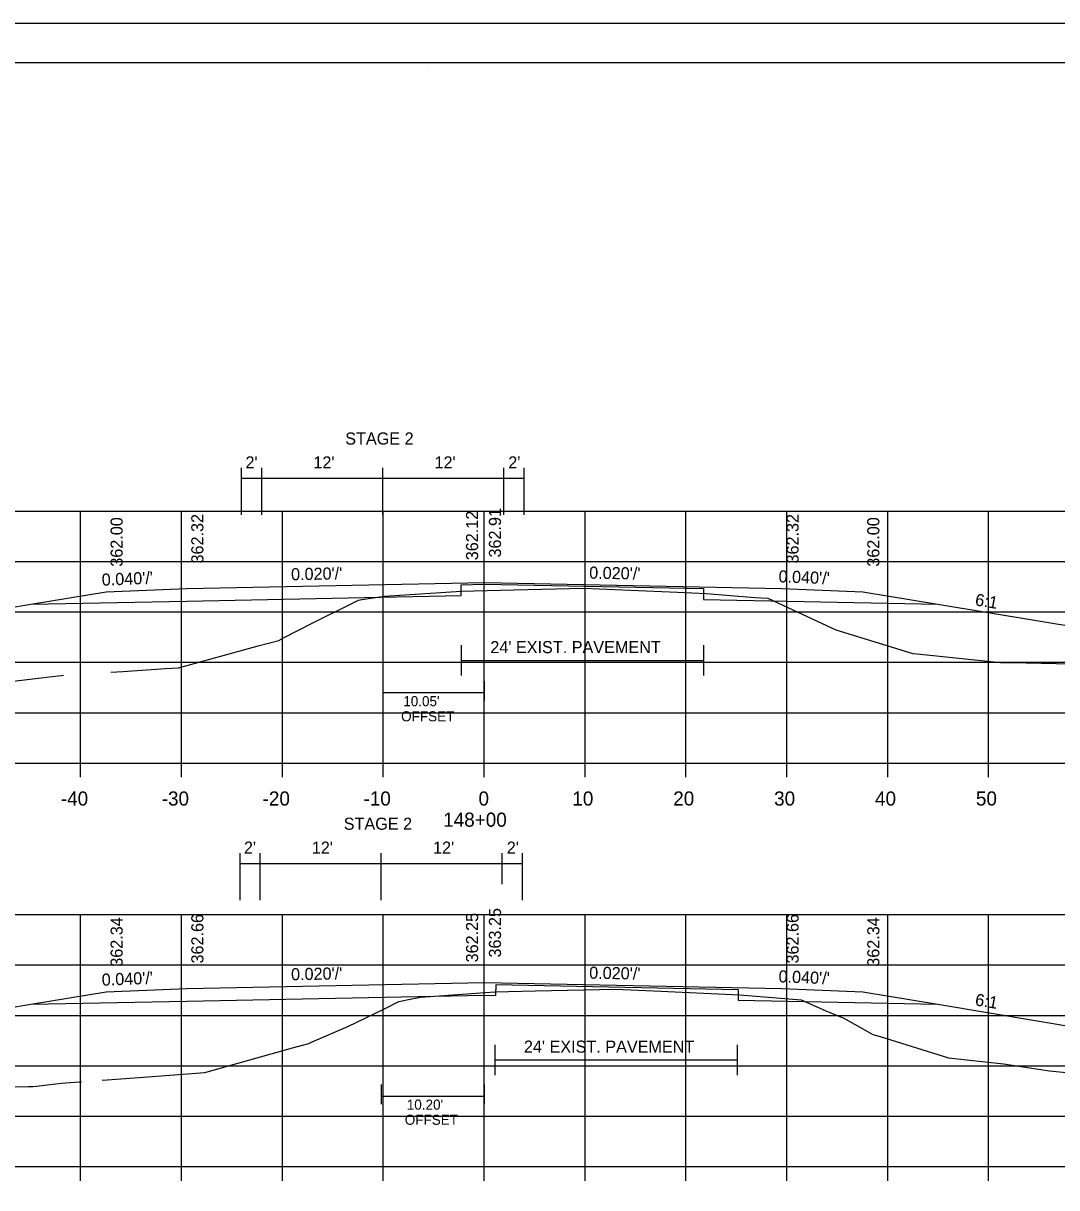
# Model space of a CAD drawing. Extents: x 1374859 to 1376773, y 382242 to 389804.
# Drawn here: x 1376088.9 to 1376191.3, y 386393.1 to 386508.5 of the extents above; entities that cross this region are included whole.
import ezdxf

# ---------------------------------------------------------------- set-up
doc = ezdxf.new("R2010")
doc.units = 0
for name, color, linetype in [('R_Axis', 7, 'Continuous'), ('R_Axis Annot', 7, 'Continuous'), ('R_Border', 7, 'Continuous'), ('R_Border Notes', 7, 'Continuous'), ('R_Draft', 7, 'Continuous'), ('R_Exist Surface', 7, 'Continuous'), ('R_Fin Surface', 7, 'Continuous'), ('R_Grid', 7, 'Continuous'), ('R_MOT', 7, 'Continuous'), ('R_No Plot', 7, 'Continuous'), ('R_Xsect Elev', 7, 'Continuous'), ('R_Xsect Slope', 7, 'Continuous')]:
    doc.layers.add(name, color=color, linetype=linetype)

msp = doc.modelspace()

# ---------------------------------------------------------------- linework, layer by layer
at = {"layer": 'R_Axis'}
for p, q in [((1375994.57, 386435.14), (1376274.57, 386435.14)), ((1376094.57, 386433.74), (1376094.57, 386435.14)), ((1376104.57, 386433.74), (1376104.57, 386435.14)), ((1376114.57, 386433.74), (1376114.57, 386435.14)), ((1376124.57, 386433.74), (1376124.57, 386435.14)), ((1376134.57, 386433.74), (1376134.57, 386435.14)), ((1376144.57, 386433.74), (1376144.57, 386435.14)), ((1376154.57, 386433.74), (1376154.57, 386435.14)), ((1376164.57, 386433.74), (1376164.57, 386435.14)), ((1376174.57, 386433.74), (1376174.57, 386435.14)), ((1376184.57, 386433.74), (1376184.57, 386435.14)), ((1375994.57, 386395.14), (1376274.57, 386395.14)), ((1376094.57, 386393.74), (1376094.57, 386395.14)), ((1376104.57, 386393.74), (1376104.57, 386395.14)), ((1376114.57, 386393.74), (1376114.57, 386395.14)), ((1376124.57, 386393.74), (1376124.57, 386395.14)), ((1376134.57, 386393.74), (1376134.57, 386395.14)), ((1376144.57, 386393.74), (1376144.57, 386395.14)), ((1376154.57, 386393.74), (1376154.57, 386395.14)), ((1376164.57, 386393.74), (1376164.57, 386395.14)), ((1376174.57, 386393.74), (1376174.57, 386395.14)), ((1376184.57, 386393.74), (1376184.57, 386395.14))]:
    msp.add_line(p, q, dxfattribs=at)
at = {"layer": 'R_Border'}
for p, q in [((1375976.57, 386504.6), (1376292.75, 386504.6)), ((1376129.09, 386504.34), (1376129.09, 386504.34)), ((1376129.09, 386504.34), (1376129.09, 386504.34))]:
    msp.add_line(p, q, dxfattribs=at)
at = {"layer": 'R_Border Notes'}
for points in [[(1376132.3, 386446.83), (1376132.3, 386443.83)], [(1376156.31, 386446.83), (1376156.31, 386443.83)], [(1376132.3, 386445.33), (1376156.31, 386445.33)], [(1376135.64, 386407.22), (1376135.64, 386404.22)], [(1376159.64, 386407.22), (1376159.64, 386404.22)], [(1376135.64, 386405.72), (1376159.64, 386405.72)]]:
    msp.add_lwpolyline(points, dxfattribs=at)
at = {"layer": 'R_Exist Surface'}
for points in [[(1376097.56, 386444.18), (1376098.76, 386444.22), (1376103, 386444.52), (1376104.27, 386444.6), (1376112.17, 386446.77), (1376114.22, 386447.3), (1376114.69, 386447.56), (1376117.58, 386449.05), (1376121.58, 386451.04), (1376122.11, 386451.3), (1376122.45, 386451.36), (1376124.68, 386451.7), (1376127.22, 386451.87), (1376132.3, 386452.21), (1376136.17, 386452.3), (1376144.4, 386452.49), (1376153.73, 386452.1), (1376156.59, 386451.98), (1376161.41, 386451.58), (1376162.68, 386451.49), (1376167.09, 386449.45), (1376169.44, 386448.35), (1376177.06, 386446.03), (1376177.1, 386446.02), (1376177.48, 386445.98), (1376185.75, 386445.11), (1376188.3, 386445.09), (1376192.83, 386444.99)], [(1375994.57, 386442.8), (1376007.7, 386442.84), (1376008.26, 386442.83), (1376009.05, 386442.83), (1376029.01, 386443.01), (1376032.33, 386442.98), (1376047.5, 386442.94), (1376059.44, 386442.96), (1376065.56, 386443.09), (1376078.87, 386443.14), (1376082.7, 386443.16), (1376085.49, 386443.17), (1376086.97, 386443.17), (1376087.2, 386443.17), (1376087.37, 386443.2), (1376090.65, 386443.6), (1376091.79, 386443.74), (1376092.36, 386443.81), (1376092.66, 386443.84), (1376092.86, 386443.86)], [(1376096.7, 386403.71), (1376097.19, 386403.75), (1376098.1, 386403.82), (1376100.37, 386403.98), (1376106.87, 386404.47), (1376115.58, 386406.91), (1376117.19, 386407.36), (1376117.52, 386407.5), (1376121.05, 386409.03), (1376124.68, 386410.8), (1376126.1, 386411.51), (1376127.39, 386411.78), (1376128.26, 386411.96), (1376133.33, 386412.31), (1376135.64, 386412.46), (1376139.67, 386412.56), (1376147.58, 386412.73), (1376151.37, 386412.57), (1376159.9, 386412.19), (1376163.54, 386411.89), (1376166, 386411.69), (1376168.45, 386410.59), (1376170.23, 386409.87), (1376172.87, 386408.39), (1376173.1, 386408.25), (1376173.81, 386408.03), (1376180.6, 386405.94), (1376186.03, 386405.33), (1376190.62, 386404.64), (1376193.61, 386404.34)], [(1375994.57, 386402.62), (1376001.33, 386402.64), (1376009.06, 386402.67), (1376011.46, 386402.68), (1376019.91, 386402.72), (1376032.69, 386402.78), (1376039.85, 386402.82), (1376050.5, 386402.85), (1376063.28, 386402.91), (1376068.8, 386402.93), (1376073.68, 386402.96), (1376085.94, 386403.06), (1376089.36, 386403.09), (1376089.82, 386403.08), (1376090.21, 386403.12), (1376092.67, 386403.41), (1376093.97, 386403.51), (1376094.47, 386403.55), (1376094.67, 386403.56)]]:
    msp.add_lwpolyline(points, dxfattribs=at)
at = {"layer": 'R_Fin Surface'}
for points in [[(1376048.6, 386442.95), (1376053.55, 386441.3), (1376075.09, 386448.48), (1376089.65, 386450.9), (1376097.09, 386452.14), (1376105.09, 386452.46), (1376134.59, 386453.05), (1376164.09, 386452.46), (1376172.09, 386452.14), (1376179.52, 386450.9), (1376194.09, 386448.48), (1376212.49, 386442.34), (1376218.21, 386444.25)], [(1376089.65, 386450.9), (1376105.1, 386451.21), (1376132.3, 386451.76), (1376132.3, 386452.84), (1376134.58, 386452.88), (1376156.31, 386452.45), (1376156.31, 386451.37), (1376179.52, 386450.9)], [(1376046.76, 386402.84), (1376051.96, 386401.1), (1376075.09, 386408.81), (1376089.65, 386411.24), (1376097.09, 386412.48), (1376105.09, 386412.8), (1376134.59, 386413.39), (1376164.09, 386412.8), (1376172.09, 386412.48), (1376179.52, 386411.24), (1376194.09, 386408.81), (1376214.1, 386402.14), (1376220.65, 386404.32)], [(1376134.58, 386412.14), (1376135.74, 386412.12), (1376135.75, 386413.2), (1376159.75, 386412.72), (1376159.76, 386411.64), (1376179.51, 386411.24)], [(1376089.65, 386411.24), (1376105.1, 386411.55), (1376134.58, 386412.14)]]:
    msp.add_lwpolyline(points, dxfattribs=at)
at = {"layer": 'R_Grid'}
for p, q in [((1375994.57, 386460.14), (1376274.57, 386460.14)), ((1376094.57, 386435.14), (1376094.57, 386460.14)), ((1376104.57, 386435.14), (1376104.57, 386460.14)), ((1376114.57, 386435.14), (1376114.57, 386460.14)), ((1376124.57, 386435.14), (1376124.57, 386460.14)), ((1376134.57, 386435.14), (1376134.57, 386460.14)), ((1376144.57, 386435.14), (1376144.57, 386460.14)), ((1376154.57, 386435.14), (1376154.57, 386460.14)), ((1376164.57, 386435.14), (1376164.57, 386460.14)), ((1376174.57, 386435.14), (1376174.57, 386460.14)), ((1376184.57, 386435.14), (1376184.57, 386460.14)), ((1375994.57, 386455.14), (1376274.57, 386455.14)), ((1375994.57, 386450.14), (1376274.57, 386450.14)), ((1375994.57, 386445.14), (1376274.57, 386445.14)), ((1375994.57, 386440.14), (1376274.57, 386440.14)), ((1375994.57, 386435.14), (1376274.57, 386435.14)), ((1375994.57, 386420.14), (1376274.57, 386420.14)), ((1376094.57, 386395.14), (1376094.57, 386420.14)), ((1376104.57, 386395.14), (1376104.57, 386420.14)), ((1376114.57, 386395.14), (1376114.57, 386420.14)), ((1376124.57, 386395.14), (1376124.57, 386420.14)), ((1376134.57, 386395.14), (1376134.57, 386420.14)), ((1376144.57, 386395.14), (1376144.57, 386420.14)), ((1376154.57, 386395.14), (1376154.57, 386420.14)), ((1376164.57, 386395.14), (1376164.57, 386420.14)), ((1376174.57, 386395.14), (1376174.57, 386420.14)), ((1376184.57, 386395.14), (1376184.57, 386420.14)), ((1375994.57, 386415.14), (1376274.57, 386415.14)), ((1375994.57, 386410.14), (1376274.57, 386410.14)), ((1375994.57, 386405.14), (1376274.57, 386405.14)), ((1375994.57, 386400.14), (1376274.57, 386400.14)), ((1375994.57, 386395.14), (1376274.57, 386395.14))]:
    msp.add_line(p, q, dxfattribs=at)
at = {"layer": 'R_MOT'}
for p, q in [((1376110.52, 386459.77), (1376110.52, 386464.41)), ((1376110.52, 386463.41), (1376138.52, 386463.41)), ((1376112.52, 386459.77), (1376112.52, 386464.41)), ((1376124.52, 386459.77), (1376124.52, 386464.41)), ((1376136.52, 386459.77), (1376136.52, 386464.41)), ((1376138.52, 386459.77), (1376138.52, 386464.41)), ((1376124.52, 386443.28), (1376124.52, 386441.35)), ((1376134.57, 386443.28), (1376134.57, 386441.35)), ((1376134.57, 386442.1), (1376124.52, 386442.1)), ((1376110.37, 386421.57), (1376110.37, 386426.21)), ((1376112.37, 386421.57), (1376112.37, 386426.21)), ((1376124.37, 386421.57), (1376124.37, 386426.21)), ((1376136.37, 386423.16), (1376136.37, 386426.21)), ((1376138.37, 386421.57), (1376138.37, 386426.21)), ((1376110.37, 386425.21), (1376138.37, 386425.21)), ((1376124.37, 386403.28), (1376124.37, 386401.35)), ((1376134.57, 386403.28), (1376134.57, 386401.35)), ((1376134.57, 386402.1), (1376124.37, 386402.1))]:
    msp.add_line(p, q, dxfattribs=at)
at = {"layer": 'R_No Plot'}
msp.add_line((1375964.17, 386508.5), (1376297.5, 386508.5), dxfattribs=at)
for points in [[(1375964.16, 386508.5), (1376297.5, 386508.5), (1376297.5, 386295.16), (1375964.16, 386295.16)], [(1376210.49, 386504.6), (1376210.49, 386494.72), (1376246.22, 386494.72), (1376246.22, 386491.8), (1376269.42, 386491.8), (1376269.42, 386467.47), (1376292.75, 386467.47), (1376292.75, 386299.14), (1375976.57, 386299.14), (1375976.57, 386504.6)]]:
    msp.add_lwpolyline(points, close=True, dxfattribs=at)

# ---------------------------------------------------------------- texts
at = {"layer": 'R_Axis Annot'}
for s, p in [('-40', (1376092.61, 386430.94)), ('-30', (1376102.61, 386430.94)), ('-20', (1376112.61, 386430.94)), ('-10', (1376122.61, 386430.94)), ('0', (1376134.01, 386430.94)), ('10', (1376143.31, 386430.94)), ('20', (1376153.31, 386430.94)), ('30', (1376163.31, 386430.94)), ('40', (1376173.31, 386430.94)), ('50', (1376183.31, 386430.94)), ('148+00', (1376130.51, 386428.84))]:
    msp.add_text(s, height=1.4, dxfattribs=at).set_placement(p)
at = {"layer": 'R_Border Notes'}
for p in [(1376135.18, 386446.05), (1376138.51, 386406.44)]:
    msp.add_text("24' EXIST. PAVEMENT", height=1.2, rotation=0, dxfattribs=at).set_placement(p)
at = {"layer": 'R_Draft'}
for s, p in [("10.05'", (1376126.55, 386440.79)), ('OFFSET', (1376126.34, 386439.29)), ("10.20'", (1376126.9, 386400.79)), ('OFFSET', (1376126.7, 386399.29))]:
    msp.add_text(s, height=1, dxfattribs=at).set_placement(p)
at = {"layer": 'R_MOT'}
for p in [(1376120.8, 386466.73), (1376120.65, 386428.54)]:
    msp.add_text('STAGE 2', height=1.2, rotation=0, dxfattribs=at).set_placement(p)
for s, p in [("2'", (1376110.91, 386464.36)), ("12'", (1376117.64, 386464.36)), ("12'", (1376129.65, 386464.36)), ("2'", (1376136.96, 386464.36)), ("2'", (1376110.76, 386426.17)), ("12'", (1376117.49, 386426.17)), ("12'", (1376129.5, 386426.17)), ("2'", (1376136.81, 386426.17))]:
    msp.add_text(s, height=1.2, dxfattribs=at).set_placement(p)
at = {"layer": 'R_Xsect Elev'}
for s, p in [('362.12', (1376133.97, 386455.26)), ('362.91', (1376136.24, 386455.53)), ('362.00', (1376098.74, 386454.62)), ('362.32', (1376106.74, 386454.94)), ('362.32', (1376165.74, 386454.94)), ('362.00', (1376173.74, 386454.62)), ('363.25', (1376136.24, 386415.87)), ('362.34', (1376098.74, 386414.96)), ('362.66', (1376106.74, 386415.28)), ('362.25', (1376133.97, 386415.39)), ('362.66', (1376165.74, 386415.28)), ('362.34', (1376173.74, 386414.96))]:
    msp.add_text(s, height=1.2, rotation=90, dxfattribs=at).set_placement(p)
at = {"layer": 'R_Xsect Slope'}
for s, rotation, p in [("0.040'/'", 2.2906, (1376096.69, 386452.73)), ("0.020'/'", 1.1458, (1376115.44, 386453.27)), ("0.020'/'", 358.8542, (1376144.97, 386453.44)), ("0.040'/'", 357.7094, (1376163.73, 386453.08)), ('6:1', 350.5358, (1376183.17, 386450.8)), ("0.020'/'", 1.1458, (1376115.44, 386413.61)), ("0.020'/'", 358.8542, (1376144.97, 386413.78)), ("0.040'/'", 2.2906, (1376096.69, 386413.07)), ("0.040'/'", 357.7094, (1376163.73, 386413.42)), ('6:1', 350.5358, (1376183.17, 386411.14))]:
    msp.add_text(s, height=1.2, rotation=rotation, dxfattribs=at).set_placement(p)

doc.saveas('drawing.dxf')
